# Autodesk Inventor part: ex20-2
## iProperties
Created: 2006-04
Part Number: ex20-2
Document SubType Name: Modeling
Designer: E. MOSS
Project: EVERGREEN VALLEY COLLEGE
Description: PLATE
Authority: MS. TEACHER
Author: E. MOSS
Revision Number: A
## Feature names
1. Extrusion1
2. Hole1
3. Extrusion2
